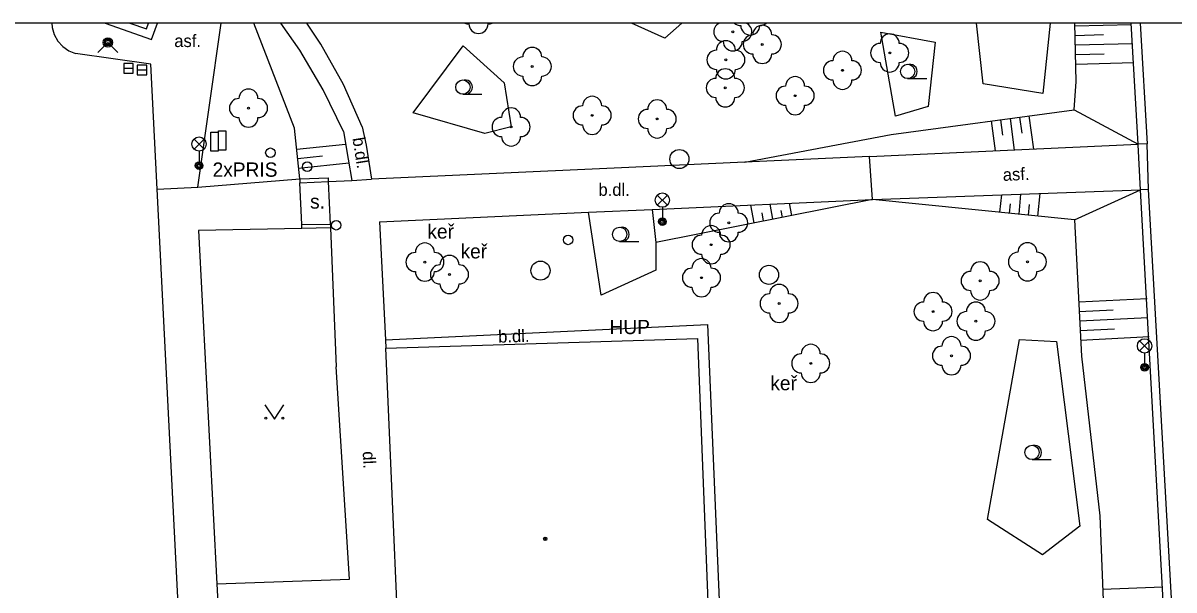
# Model space of a CAD drawing. Extents: x -599951 to -598963, y -1164095 to -1162939.
# Drawn here: x -599318.9 to -599258.6, y -1162969.1 to -1162939.4 of the extents above; entities that cross this region are included whole.
import ezdxf

# ---------------------------------------------------------------- set-up
doc = ezdxf.new("R2010")
doc.units = 0
for name, color, linetype in [('Level 10', 7, 'Continuous'), ('Level 11', 7, 'Continuous'), ('Level 14', 7, 'Continuous'), ('Level 15', 7, 'Continuous'), ('Level 21', 7, 'Continuous'), ('Level 22', 7, 'Continuous'), ('Level 24', 7, 'Continuous'), ('Level 27', 7, 'Continuous'), ('Level 28', 7, 'Continuous'), ('Level 31', 7, 'Continuous'), ('Level 33', 7, 'Continuous'), ('Level 36', 7, 'Continuous'), ('Level 39', 7, 'Continuous'), ('Level 40', 7, 'Continuous'), ('Level 41', 7, 'Continuous'), ('Level 42', 7, 'Continuous'), ('Level 5', 7, 'Continuous'), ('Level 7', 7, 'Continuous'), ('Vrstva 53', 7, 'Continuous')]:
    doc.layers.add(name, color=color, linetype=linetype)

msp = doc.modelspace()

# ---------------------------------------------------------------- linework, layer by layer
at = {"layer": 'Level 10'}
for points in [[(-599317.387, -1162939.4), (-599317.371, -1162939.64), (-599317.26, -1162940.01), (-599317.073, -1162940.343), (-599316.817, -1162940.629), (-599316.504, -1162940.851), (-599316.15, -1162941)], [(-599312.19, -1162941.56), (-599316.15, -1162941)], [(-599311.86, -1162948.11), (-599312.19, -1162941.56)], [(-599309.21, -1163000.62), (-599311.86, -1162948.11)]]:
    msp.add_lwpolyline(points, dxfattribs=at)
at = {"layer": 'Level 11'}
for p, q in [((-599314.601, -1162939.4), (-599312.16, -1162940.27)), ((-599313.293, -1162939.4), (-599312.43, -1162939.71)), ((-599312.43, -1162939.71), (-599312.319, -1162939.4)), ((-599312.16, -1162940.27), (-599311.85, -1162939.4)), ((-599309.74, -1162948), (-599308.504, -1162939.4)), ((-599304.66, -1162944.91), (-599306.796, -1162939.4)), ((-599260.44, -1162945.75), (-599260.8, -1162939.4)), ((-599260.326, -1162939.4), (-599259.97, -1162945.73))]:
    msp.add_line(p, q, dxfattribs=at)
for points in [[(-599302.1, -1162945.09), (-599303.16, -1162942.91), (-599304.39, -1162940.82), (-599305.375, -1162939.4)], [(-599301.12, -1162944.84), (-599302.1, -1162942.63), (-599303.28, -1162940.51), (-599304.026, -1162939.4)], [(-599302.1, -1162945.09), (-599301.85, -1162946.53), (-599301.66, -1162947.65)], [(-599301.12, -1162944.84), (-599300.91, -1162945.8), (-599300.63, -1162947.59)], [(-599274.52, -1162946.4), (-599260.44, -1162945.75)], [(-599259.97, -1162945.73), (-599260.44, -1162945.75)], [(-599260.31, -1162948.14), (-599260.44, -1162945.78), (-599260.44, -1162945.75)], [(-599259.89, -1162948.12), (-599259.97, -1162945.73)], [(-599274.52, -1162946.4), (-599281.05, -1162946.69), (-599287.91, -1162947.01), (-599300.63, -1162947.59)], [(-599274.37, -1162948.65), (-599274.52, -1162946.4)], [(-599309.74, -1162948), (-599304.39, -1162947.57)], [(-599302.88, -1162947.71), (-599301.66, -1162947.65)], [(-599302.78, -1162949.94), (-599302.88, -1162947.71)], [(-599301.66, -1162947.65), (-599300.63, -1162947.59)], [(-599311.86, -1162948.11), (-599309.74, -1162948)], [(-599304.28, -1162949.97), (-599304.38, -1162947.77)], [(-599300.21, -1162949.82), (-599289.26, -1162949.31), (-599285.92, -1162949.17), (-599274.37, -1162948.65), (-599260.31, -1162948.14)], [(-599259.89, -1162948.12), (-599260.31, -1162948.14)], [(-599256.88, -1163010.08), (-599257.66, -1162996.31), (-599260.31, -1162948.14)], [(-599256.88, -1163010.08), (-599256.44, -1163010.06), (-599257.19, -1162996.28), (-599259.89, -1162948.12)], [(-599300.21, -1162949.82), (-599299.89, -1162956), (-599299.87, -1162956.44)], [(-599304.28, -1162950.17), (-599309.7, -1162950.27)], [(-599309.7, -1162950.27), (-599308.74, -1162968.8)], [(-599302.78, -1162950.14), (-599302.48, -1162957.43)], [(-599299.89, -1162956), (-599283.02, -1162955.21), (-599282.39, -1162970.07), (-599282.07, -1162977.73), (-599282.69, -1162977.76)], [(-599301.79, -1162968.55), (-599302.48, -1162957.43)], [(-599308.74, -1162968.8), (-599301.79, -1162968.55)], [(-599308.74, -1162968.8), (-599308.62, -1162971.1)]]:
    msp.add_lwpolyline(points, dxfattribs=at)
at = {"layer": 'Level 14'}
for points in [[(-599281.05, -1162946.69), (-599273.39, -1162945.24), (-599263.79, -1162943.95), (-599263.68, -1162942.46), (-599263.76, -1162939.4)], [(-599263.79, -1162943.95), (-599260.44, -1162945.75)], [(-599304.39, -1162947.57), (-599304.66, -1162944.91)], [(-599263.77, -1162949.71), (-599260.31, -1162948.14)], [(-599274.37, -1162948.65), (-599285.72, -1162950.91)], [(-599263.77, -1162949.71), (-599274.37, -1162948.65)], [(-599263.77, -1162949.71), (-599263.41, -1162956.86)], [(-599263.41, -1162956.86), (-599262.45, -1162965.24), (-599261.69, -1162984.26)]]:
    msp.add_lwpolyline(points, dxfattribs=at)
at = {"layer": 'Level 15'}
for points in [[(-599263.76, -1162939.55), (-599260.79, -1162939.47)], [(-599263.74, -1162940.05), (-599262.25, -1162940.01)], [(-599263.73, -1162940.55), (-599260.73, -1162940.47)], [(-599263.72, -1162941.05), (-599262.21, -1162941.01)], [(-599263.7, -1162941.55), (-599260.67, -1162941.47)], [(-599268.14, -1162944.53), (-599267.93, -1162946.1)], [(-599267.65, -1162944.47), (-599267.54, -1162945.27)], [(-599267.15, -1162944.4), (-599266.93, -1162946.06)], [(-599266.66, -1162944.34), (-599266.54, -1162945.18)], [(-599266.16, -1162944.27), (-599265.93, -1162946.01)], [(-599304.55, -1162946.01), (-599301.99, -1162945.75)], [(-599304.5, -1162946.5), (-599303.2, -1162946.37)], [(-599304.45, -1162947), (-599301.82, -1162946.73)], [(-599279.58, -1162949.69), (-599279.73, -1162948.89)], [(-599278.6, -1162949.49), (-599278.72, -1162948.85)], [(-599267.68, -1162949.32), (-599267.59, -1162948.4)], [(-599267.18, -1162949.37), (-599267.13, -1162948.88)], [(-599266.68, -1162949.42), (-599266.58, -1162948.37)], [(-599266.19, -1162949.47), (-599266.13, -1162948.91)], [(-599265.69, -1162949.52), (-599265.57, -1162948.33)], [(-599280.56, -1162949.88), (-599280.75, -1162948.94)], [(-599280.07, -1162949.78), (-599280.15, -1162949.35)], [(-599279.09, -1162949.59), (-599279.16, -1162949.23)], [(-599263.55, -1162954.02), (-599259.97, -1162953.84)], [(-599263.53, -1162954.52), (-599261.74, -1162954.43)], [(-599263.5, -1162955.02), (-599259.92, -1162954.84)], [(-599263.48, -1162955.52), (-599261.68, -1162955.43)], [(-599263.45, -1162956.02), (-599259.86, -1162955.84)], [(-599262.3, -1162969.07), (-599259.15, -1162968.95)]]:
    msp.add_lwpolyline(points, dxfattribs=at)
at = {"layer": 'Level 21'}
for points in [[(-599284.359, -1162939.4), (-599285.25, -1162940.19), (-599287, -1162939.4)], [(-599265.042, -1162939.4), (-599265.44, -1162943.1), (-599268.57, -1162942.58), (-599268.911, -1162939.4)], [(-599271.07, -1162940.41), (-599271.44, -1162943.77), (-599273.15, -1162944.28), (-599273.92, -1162939.88)], [(-599273.92, -1162939.88), (-599271.07, -1162940.41)], [(-599293.31, -1162944.85), (-599294.68, -1162945.19), (-599298.44, -1162944.1), (-599295.82, -1162940.6), (-599293.67, -1162942.54), (-599293.31, -1162944.85)], [(-599285.92, -1162949.17), (-599285.72, -1162950.91), (-599285.73, -1162952.36), (-599288.58, -1162953.67), (-599289.26, -1162949.31)], [(-599268.34, -1162965.42), (-599266.66, -1162955.99), (-599264.71, -1162956.1), (-599263.5, -1162965.78), (-599265.45, -1162967.28), (-599268.34, -1162965.42)]]:
    msp.add_lwpolyline(points, dxfattribs=at)
at = {"layer": 'Level 22'}
for centre in [(-599281.69, -1162939.86), (-599280.14, -1162940.52), (-599273.46, -1162940.97), (-599292.2, -1162941.68), (-599282.05, -1162941.33), (-599275.94, -1162941.88), (-599282.08, -1162942.8), (-599278.42, -1162943.21), (-599307.08, -1162943.86), (-599289.06, -1162944.24), (-599285.65, -1162944.43), (-599293.31, -1162944.85), (-599281.9, -1162949.87), (-599282.82, -1162951.02), (-599297.83, -1162951.93), (-599266.24, -1162951.92), (-599296.54, -1162952.58), (-599283.33, -1162952.75), (-599268.72, -1162952.92), (-599279.26, -1162954.1), (-599271.19, -1162954.53), (-599268.94, -1162955.03), (-599277.6, -1162957.24), (-599270.22, -1162956.84)]:
    msp.add_circle(centre, 0.05, dxfattribs=at)
for centre, start, end in [((-599295.52, -1162938.95), 244.14493, 270), ((-599295.02, -1162939.45), 180, 0), ((-599294.52, -1162938.95), 270, 295.85507), ((-599282.19, -1162939.86), 113.05929, 270), ((-599281.27, -1162939.03), 227.7229, 270), ((-599280.77, -1162939.53), 180, 0), ((-599281.19, -1162939.86), 270, 66.94071), ((-599280.14, -1162940.02), 0, 180), ((-599280.27, -1162939.03), 270, 312.2771), ((-599282.05, -1162940.83), 0, 180), ((-599281.69, -1162940.36), 180, 0), ((-599280.64, -1162940.52), 90, 270), ((-599279.64, -1162940.52), 270, 90), ((-599273.96, -1162940.97), 90, 270), ((-599273.46, -1162940.47), 0, 180), ((-599272.96, -1162940.97), 270, 90), ((-599292.2, -1162941.18), 0, 180), ((-599282.55, -1162941.33), 90, 270), ((-599281.55, -1162941.33), 270, 90), ((-599280.14, -1162941.02), 180, 0), ((-599275.94, -1162941.38), 0, 180), ((-599292.7, -1162941.68), 90, 270), ((-599291.7, -1162941.68), 270, 90), ((-599276.44, -1162941.88), 90, 270), ((-599275.44, -1162941.88), 270, 90), ((-599273.46, -1162941.47), 180, 0), ((-599292.2, -1162942.18), 180, 0), ((-599282.08, -1162942.3), 0, 180), ((-599282.05, -1162941.83), 180, 0), ((-599278.42, -1162942.71), 0, 180), ((-599307.08, -1162943.36), 0, 180), ((-599282.58, -1162942.8), 90, 270), ((-599281.58, -1162942.8), 270, 90), ((-599278.92, -1162943.21), 90, 270), ((-599277.92, -1162943.21), 270, 90), ((-599275.94, -1162942.38), 180, 0), ((-599307.58, -1162943.86), 90, 270), ((-599306.58, -1162943.86), 270, 90), ((-599289.06, -1162943.74), 0, 180), ((-599285.65, -1162943.93), 0, 180), ((-599282.08, -1162943.3), 180, 0), ((-599293.31, -1162944.35), 0, 180), ((-599289.56, -1162944.24), 90, 270), ((-599288.56, -1162944.24), 270, 90), ((-599286.15, -1162944.43), 90, 270), ((-599285.15, -1162944.43), 270, 90), ((-599278.42, -1162943.71), 180, 0), ((-599307.08, -1162944.36), 180, 0), ((-599293.81, -1162944.85), 90, 270), ((-599292.81, -1162944.85), 270, 90), ((-599289.06, -1162944.74), 180, 0), ((-599285.65, -1162944.93), 180, 0), ((-599293.31, -1162945.35), 180, 0), ((-599281.9, -1162949.37), 0, 180), ((-599282.4, -1162949.87), 90, 270), ((-599281.4, -1162949.87), 270, 90), ((-599282.82, -1162950.52), 0, 180), ((-599283.32, -1162951.02), 90, 270), ((-599281.9, -1162950.37), 180, 0), ((-599282.32, -1162951.02), 270, 90), ((-599297.83, -1162951.43), 0, 180), ((-599266.24, -1162951.42), 0, 180), ((-599298.33, -1162951.93), 90, 270), ((-599297.33, -1162951.93), 270, 90), ((-599296.54, -1162952.08), 0, 180), ((-599283.33, -1162952.25), 0, 180), ((-599282.82, -1162951.52), 180, 0), ((-599268.72, -1162952.42), 0, 180), ((-599266.74, -1162951.92), 90, 270), ((-599265.74, -1162951.92), 270, 90), ((-599297.83, -1162952.43), 180, 0), ((-599297.04, -1162952.58), 90, 270), ((-599296.04, -1162952.58), 270, 90), ((-599283.83, -1162952.75), 90, 270), ((-599282.83, -1162952.75), 270, 90), ((-599269.22, -1162952.92), 90, 270), ((-599268.22, -1162952.92), 270, 90), ((-599266.24, -1162952.42), 180, 0), ((-599296.54, -1162953.08), 180, 0), ((-599279.26, -1162953.6), 0, 180), ((-599283.33, -1162953.25), 180, 0), ((-599279.76, -1162954.1), 90, 270), ((-599278.76, -1162954.1), 270, 90), ((-599271.19, -1162954.03), 0, 180), ((-599268.72, -1162953.42), 180, 0), ((-599271.69, -1162954.53), 90, 270), ((-599270.69, -1162954.53), 270, 90), ((-599268.94, -1162954.53), 0, 180), ((-599279.26, -1162954.6), 180, 0), ((-599269.44, -1162955.03), 90, 270), ((-599268.44, -1162955.03), 270, 90), ((-599271.19, -1162955.03), 180, 0), ((-599268.94, -1162955.53), 180, 0), ((-599270.22, -1162956.34), 0, 180), ((-599278.1, -1162957.24), 90, 270), ((-599277.6, -1162956.74), 0, 180), ((-599277.1, -1162957.24), 270, 90), ((-599270.72, -1162956.84), 90, 270), ((-599269.72, -1162956.84), 270, 90), ((-599270.22, -1162957.34), 180, 0), ((-599277.6, -1162957.74), 180, 0)]:
    msp.add_arc(centre, 0.5, start, end, dxfattribs=at)
at = {"layer": 'Level 24'}
for points in [[(-599309.06, -1162946.12), (-599309.06, -1162945.12)], [(-599309.06, -1162945.12), (-599308.67, -1162945.12)], [(-599308.67, -1162945.12), (-599308.67, -1162946.12)], [(-599308.65, -1162946.06), (-599308.65, -1162945.06)], [(-599308.65, -1162945.06), (-599308.26, -1162945.06)], [(-599308.26, -1162945.06), (-599308.26, -1162946.06)], [(-599308.67, -1162946.12), (-599309.06, -1162946.12)], [(-599308.26, -1162946.06), (-599308.65, -1162946.06)]]:
    msp.add_lwpolyline(points, dxfattribs=at)
at = {"layer": 'Level 27'}
for p, q in [((-599313.62, -1162941.77), (-599313.12, -1162941.77)), ((-599312.91, -1162941.86), (-599312.41, -1162941.86))]:
    msp.add_line(p, q, dxfattribs=at)
for points in [[(-599313.62, -1162942.02), (-599313.12, -1162942.02), (-599313.12, -1162941.52), (-599313.62, -1162941.52)], [(-599312.91, -1162942.11), (-599312.41, -1162942.11), (-599312.41, -1162941.61), (-599312.91, -1162941.61)]]:
    msp.add_lwpolyline(points, close=True, dxfattribs=at)
for centre in [(-599284.49, -1162946.53), (-599291.77, -1162952.38), (-599279.79, -1162952.6)]:
    msp.add_circle(centre, 0.5, dxfattribs=at)
at = {"layer": 'Level 28'}
for centre in [(-599305.93, -1162946.2), (-599302.48, -1162950), (-599290.32, -1162950.77)]:
    msp.add_circle(centre, 0.25, dxfattribs=at)
at = {"layer": 'Level 31'}
msp.add_lwpolyline([(-599314.98, -1162940.95), (-599314.45, -1162940.42), (-599313.92, -1162940.95)], dxfattribs=at)
for centre, radius in [((-599314.45, -1162940.42), 0.25), ((-599314.45, -1162940.42), 0.18), ((-599314.45, -1162940.42), 0.11), ((-599304, -1162946.93), 0.25)]:
    msp.add_circle(centre, radius, dxfattribs=at)
at = {"layer": 'Level 33'}
for p, q in [((-599309.935, -1162946.01), (-599309.405, -1162945.48)), ((-599309.935, -1162945.48), (-599309.405, -1162946.01)), ((-599309.67, -1162946.12), (-599309.67, -1162946.87)), ((-599285.645, -1162948.95), (-599285.115, -1162948.42)), ((-599285.645, -1162948.42), (-599285.115, -1162948.95)), ((-599285.38, -1162949.06), (-599285.38, -1162949.81)), ((-599260.365, -1162956.59), (-599259.835, -1162956.06)), ((-599260.365, -1162956.06), (-599259.835, -1162956.59)), ((-599260.1, -1162956.7), (-599260.1, -1162957.45))]:
    msp.add_line(p, q, dxfattribs=at)
for centre, radius in [((-599309.67, -1162945.745), 0.375), ((-599309.67, -1162946.87), 0.2), ((-599309.67, -1162946.87), 0.145), ((-599309.67, -1162946.87), 0.0876), ((-599285.38, -1162948.685), 0.375), ((-599285.38, -1162949.81), 0.2), ((-599285.38, -1162949.81), 0.145), ((-599285.38, -1162949.81), 0.0876), ((-599260.1, -1162956.325), 0.375), ((-599260.1, -1162957.45), 0.2), ((-599260.1, -1162957.45), 0.145), ((-599260.1, -1162957.45), 0.0876)]:
    msp.add_circle(centre, radius, dxfattribs=at)
at = {"layer": 'Level 36'}
for p, q in [((-599272.52, -1162942.315), (-599271.52, -1162942.315)), ((-599295.84, -1162943.135), (-599294.84, -1162943.135)), ((-599287.62, -1162950.855), (-599286.62, -1162950.855)), ((-599266, -1162962.285), (-599265, -1162962.285))]:
    msp.add_line(p, q, dxfattribs=at)
msp.add_lwpolyline([(-599306.22, -1162959.41), (-599305.72, -1162960.16), (-599305.22, -1162959.41)], dxfattribs=at)
for centre, radius in [((-599272.52, -1162941.94), 0.375), ((-599295.84, -1162942.76), 0.375), ((-599287.62, -1162950.48), 0.375), ((-599306.17, -1162960.11), 0.05), ((-599305.271, -1162960.11), 0.05), ((-599266, -1162961.91), 0.375)]:
    msp.add_circle(centre, radius, dxfattribs=at)
for centre in [(-599272.395, -1162941.94), (-599295.715, -1162942.76), (-599287.495, -1162950.48), (-599265.875, -1162961.91)]:
    msp.add_arc(centre, 0.375, 260.40593, 99.59407, dxfattribs=at)
at = {"layer": 'Level 39'}
for radius in [0.09, 0.0398]:
    msp.add_circle((-599291.52, -1162966.44), radius, dxfattribs=at)
at = {"layer": 'Level 5'}
for points in [[(-599299.87, -1162956.44), (-599283.54, -1162955.93)], [(-599283.54, -1162955.93), (-599282.69, -1162977.76)], [(-599298.92, -1162978.56), (-599299.87, -1162956.44)]]:
    msp.add_lwpolyline(points, dxfattribs=at)
at = {"layer": 'Level 7'}
for points in [[(-599304.39, -1162947.57), (-599302.89, -1162947.51)], [(-599304.39, -1162947.57), (-599304.38, -1162947.77)], [(-599304.38, -1162947.77), (-599302.88, -1162947.71)], [(-599302.88, -1162947.71), (-599302.89, -1162947.51)], [(-599304.28, -1162950.17), (-599304.28, -1162949.97), (-599302.78, -1162949.94), (-599302.78, -1162950.14)], [(-599302.78, -1162950.14), (-599304.28, -1162950.17)]]:
    msp.add_lwpolyline(points, dxfattribs=at)
at = {"layer": 'Vrstva 53'}
msp.add_lwpolyline([(-599951.125, -1164094.695), (-598963.215, -1164094.695), (-598963.215, -1162939.4), (-599951.125, -1162939.4)], close=True, dxfattribs=at)

# ---------------------------------------------------------------- texts
at = {"layer": 'Level 40'}
for s, p in [('asf.', (-599310.97, -1162940.66)), ('b.dl.', (-599288.73, -1162948.46))]:
    msp.add_text(s, height=0.65, dxfattribs=at).set_placement(p)
for s, rotation, p in [('b.dl.', 278.89042, (-599301.63, -1162945.44)), ('asf.', 2.60071, (-599267.52, -1162947.68)), ('b.dl.', 1.78883, (-599293.98, -1162956.16)), ('dl.', 272.53, (-599301.09, -1162961.86))]:
    msp.add_text(s, height=0.65, rotation=rotation, dxfattribs=at).set_placement(p)
at = {"layer": 'Level 41'}
for s, p in [('2xPRIS', (-599308.96, -1162947.46)), ('HUP', (-599288.15, -1162955.71))]:
    msp.add_text(s, height=0.75, dxfattribs=at).set_placement(p)
at = {"layer": 'Level 42'}
for s, p in [('s.', (-599303.85, -1162949.13)), ('keř', (-599297.7, -1162950.7)), ('keř', (-599295.96, -1162951.74)), ('keř', (-599279.72, -1162958.65))]:
    msp.add_text(s, height=0.75, dxfattribs=at).set_placement(p)

doc.saveas('drawing.dxf')
